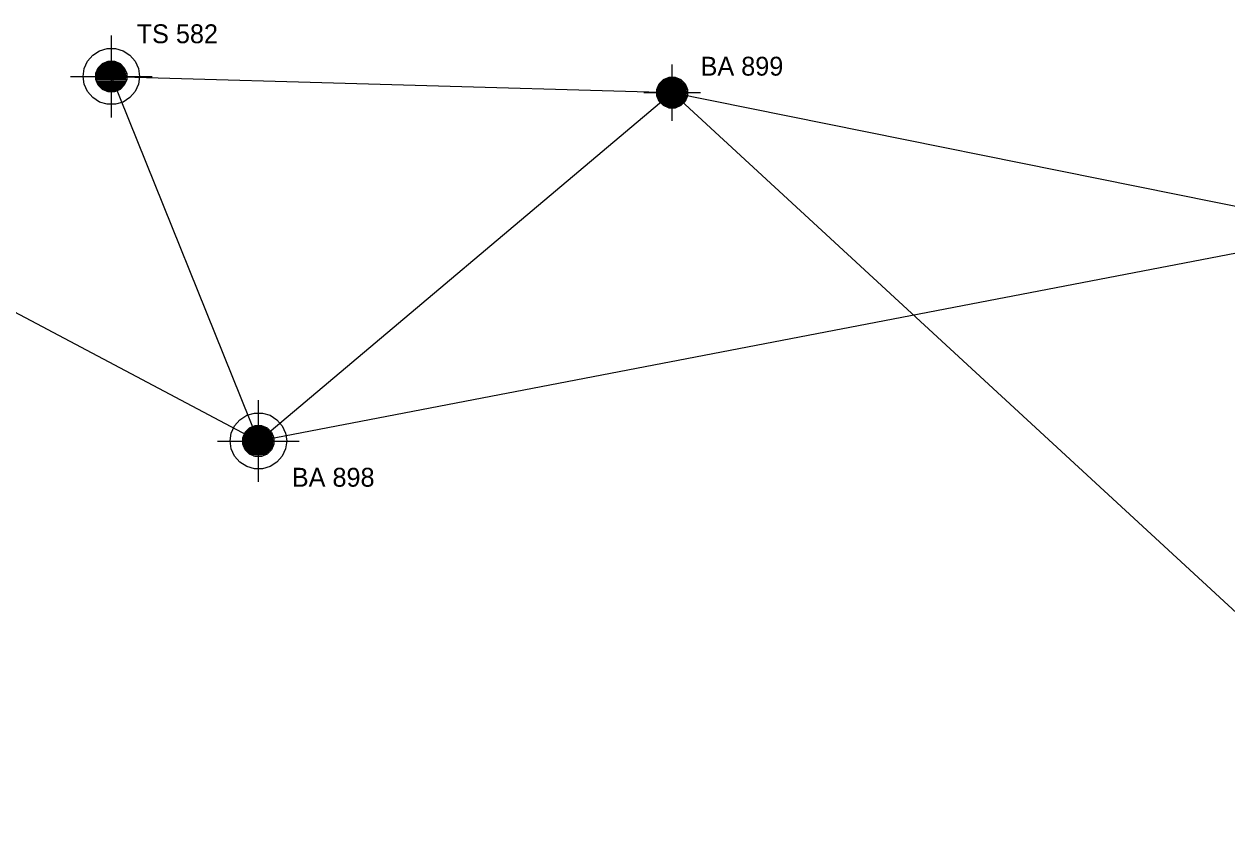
# Model space of a CAD drawing. Extents: x -346533 to -339969, y -1273090 to -1271585.
# Drawn here: x -345644.6 to -345166.4, y -1272777.1 to -1272455.2 of the extents above; entities that cross this region are included whole.
import ezdxf

# ---------------------------------------------------------------- set-up
doc = ezdxf.new("R2010")
doc.units = 0
for name, color, linetype in [('BP_11', 7, 'Continuous'), ('BP_12', 7, 'Continuous'), ('BP_14', 7, 'Continuous')]:
    doc.layers.add(name, color=color, linetype=linetype)

msp = doc.modelspace()

# ---------------------------------------------------------------- linework, layer by layer
at = {"layer": 'BP_11'}
for points in [[(-345609.9, -1272492.29), (-345609.9, -1272485.94), (-345609.9, -1272479.59), (-345609.9, -1272473.24), (-345609.9, -1272466.89), (-345609.9, -1272460.54), (-345609.9, -1272459.79)], [(-345609.9, -1272469.89), (-345608.7, -1272469.89), (-345606.45, -1272470.84), (-345604.75, -1272472.54), (-345603.8, -1272474.79), (-345603.8, -1272477.24), (-345604.75, -1272479.49), (-345606.45, -1272481.19), (-345608.7, -1272482.14), (-345611.15, -1272482.14), (-345613.4, -1272481.19), (-345615.1, -1272479.49), (-345616.05, -1272477.24), (-345616.05, -1272474.79), (-345615.1, -1272472.54), (-345613.4, -1272470.84), (-345611.15, -1272469.89), (-345609.95, -1272469.89), (-345608.15, -1272470.24), (-345611.75, -1272470.24), (-345612.55, -1272470.64), (-345607.35, -1272470.64), (-345606.55, -1272471.04), (-345612.9, -1272471.04), (-345613.35, -1272471.04), (-345613.75, -1272471.44), (-345607.4, -1272471.44), (-345606.15, -1272471.44), (-345605.75, -1272471.84), (-345612.1, -1272471.84), (-345614.15, -1272471.84), (-345614.55, -1272472.24), (-345608.2, -1272472.24), (-345605.35, -1272472.24), (-345604.95, -1272472.64), (-345611.3, -1272472.64), (-345614.95, -1272472.64), (-345614.95, -1272473.04), (-345608.6, -1272473.04), (-345604.95, -1272473.04), (-345604.55, -1272473.44), (-345610.9, -1272473.44), (-345615.35, -1272473.44), (-345615.35, -1272473.84), (-345609, -1272473.84), (-345604.55, -1272473.84), (-345604.55, -1272474.24), (-345610.9, -1272474.24), (-345615.35, -1272474.24), (-345615.75, -1272474.64), (-345609.4, -1272474.64), (-345604.15, -1272474.64), (-345604.15, -1272475.04), (-345610.5, -1272475.04), (-345615.75, -1272475.04), (-345615.75, -1272475.44), (-345609.4, -1272475.44), (-345604.15, -1272475.44), (-345604.15, -1272475.84), (-345610.5, -1272475.84), (-345615.75, -1272475.84), (-345615.75, -1272476.24), (-345609.4, -1272476.24), (-345604.15, -1272476.24), (-345604.15, -1272476.64), (-345610.5, -1272476.64), (-345615.75, -1272476.64), (-345615.75, -1272477.04), (-345609.4, -1272477.04), (-345604.15, -1272477.04), (-345604.15, -1272477.44), (-345610.5, -1272477.44), (-345615.75, -1272477.44), (-345615.75, -1272477.84), (-345609.4, -1272477.84), (-345604.15, -1272477.84), (-345604.55, -1272478.24), (-345610.9, -1272478.24), (-345615.35, -1272478.24), (-345615.35, -1272478.64), (-345609, -1272478.64), (-345604.55, -1272478.64), (-345604.95, -1272479.04), (-345611.3, -1272479.04), (-345614.95, -1272479.04), (-345614.95, -1272479.44), (-345608.6, -1272479.44), (-345604.95, -1272479.44), (-345605.35, -1272479.84), (-345611.7, -1272479.84), (-345614.55, -1272479.84), (-345614.15, -1272480.24), (-345607.8, -1272480.24), (-345605.75, -1272480.24), (-345606.15, -1272480.64), (-345612.5, -1272480.64), (-345613.75, -1272480.64), (-345613.35, -1272481.04), (-345607, -1272481.04), (-345606.55, -1272481.04)], [(-345386.94, -1272493.72), (-345386.94, -1272487.37), (-345386.94, -1272481.02), (-345386.94, -1272474.67), (-345386.94, -1272471.22)], [(-345626.15, -1272476.04), (-345619.8, -1272476.04), (-345613.45, -1272476.04), (-345607.1, -1272476.04), (-345600.75, -1272476.04), (-345594.4, -1272476.04), (-345593.65, -1272476.04)], [(-345386.94, -1272476.32), (-345385.74, -1272476.32), (-345383.49, -1272477.27), (-345381.79, -1272478.97), (-345380.84, -1272481.22), (-345380.84, -1272483.67), (-345381.79, -1272485.92), (-345383.49, -1272487.62), (-345385.74, -1272488.57), (-345388.19, -1272488.57), (-345390.44, -1272487.62), (-345392.14, -1272485.92), (-345393.09, -1272483.67), (-345393.09, -1272481.22), (-345392.14, -1272478.97), (-345390.44, -1272477.27), (-345388.19, -1272476.32), (-345386.99, -1272476.32), (-345385.19, -1272476.67), (-345388.79, -1272476.67), (-345389.59, -1272477.07), (-345384.39, -1272477.07), (-345383.59, -1272477.47), (-345389.94, -1272477.47), (-345390.39, -1272477.47), (-345390.79, -1272477.87), (-345384.44, -1272477.87), (-345383.19, -1272477.87), (-345382.79, -1272478.27), (-345389.14, -1272478.27), (-345391.19, -1272478.27), (-345391.59, -1272478.67), (-345385.24, -1272478.67), (-345382.39, -1272478.67), (-345381.99, -1272479.07), (-345388.34, -1272479.07), (-345391.99, -1272479.07), (-345391.99, -1272479.47), (-345385.64, -1272479.47), (-345381.99, -1272479.47), (-345381.59, -1272479.87), (-345387.94, -1272479.87), (-345392.39, -1272479.87), (-345392.39, -1272480.27), (-345386.04, -1272480.27), (-345381.59, -1272480.27), (-345381.19, -1272480.67), (-345387.54, -1272480.67), (-345392.79, -1272480.67), (-345392.79, -1272481.07), (-345386.44, -1272481.07), (-345381.19, -1272481.07), (-345381.19, -1272481.47), (-345387.54, -1272481.47), (-345392.79, -1272481.47), (-345392.79, -1272481.87), (-345386.44, -1272481.87), (-345381.19, -1272481.87), (-345381.19, -1272482.27), (-345387.54, -1272482.27), (-345392.79, -1272482.27), (-345392.79, -1272482.67), (-345386.44, -1272482.67), (-345381.19, -1272482.67), (-345381.19, -1272483.07), (-345387.54, -1272483.07), (-345392.79, -1272483.07), (-345392.79, -1272483.47), (-345386.44, -1272483.47), (-345381.19, -1272483.47), (-345381.19, -1272483.87), (-345387.54, -1272483.87), (-345392.79, -1272483.87), (-345392.79, -1272484.27), (-345386.44, -1272484.27), (-345381.19, -1272484.27), (-345381.59, -1272484.67), (-345387.94, -1272484.67), (-345392.39, -1272484.67), (-345392.39, -1272485.07), (-345386.04, -1272485.07), (-345381.59, -1272485.07), (-345381.99, -1272485.47), (-345388.34, -1272485.47), (-345391.99, -1272485.47), (-345391.99, -1272485.87), (-345385.64, -1272485.87), (-345381.99, -1272485.87), (-345382.39, -1272486.27), (-345388.74, -1272486.27), (-345391.59, -1272486.27), (-345391.19, -1272486.67), (-345384.84, -1272486.67), (-345382.79, -1272486.67), (-345383.19, -1272487.07), (-345389.54, -1272487.07), (-345390.79, -1272487.07), (-345390.39, -1272487.47), (-345384.04, -1272487.47), (-345383.59, -1272487.47)], [(-345606.55, -1272481.04), (-345607.35, -1272481.44), (-345612.55, -1272481.44), (-345611.75, -1272481.84), (-345608.15, -1272481.84)], [(-345398.19, -1272482.47), (-345391.84, -1272482.47), (-345385.49, -1272482.47), (-345379.14, -1272482.47), (-345375.69, -1272482.47)], [(-345383.59, -1272487.47), (-345384.39, -1272487.87), (-345389.59, -1272487.87), (-345388.79, -1272488.27), (-345385.19, -1272488.27)], [(-345551.44, -1272637.21), (-345551.44, -1272630.86), (-345551.44, -1272624.51), (-345551.44, -1272618.16), (-345551.44, -1272611.81), (-345551.44, -1272605.46), (-345551.44, -1272604.71)], [(-345551.44, -1272614.81), (-345550.24, -1272614.81), (-345547.99, -1272615.76), (-345546.29, -1272617.46), (-345545.34, -1272619.71), (-345545.34, -1272622.16), (-345546.29, -1272624.41), (-345547.99, -1272626.11), (-345550.24, -1272627.06), (-345552.69, -1272627.06), (-345554.94, -1272626.11), (-345556.64, -1272624.41), (-345557.59, -1272622.16), (-345557.59, -1272619.71), (-345556.64, -1272617.46), (-345554.94, -1272615.76), (-345552.69, -1272614.81), (-345551.49, -1272614.81), (-345549.69, -1272615.16), (-345553.29, -1272615.16), (-345554.09, -1272615.56), (-345548.89, -1272615.56), (-345548.09, -1272615.96), (-345554.44, -1272615.96), (-345554.89, -1272615.96), (-345555.29, -1272616.36), (-345548.94, -1272616.36), (-345547.69, -1272616.36), (-345547.29, -1272616.76), (-345553.64, -1272616.76), (-345555.69, -1272616.76), (-345556.09, -1272617.16), (-345549.74, -1272617.16), (-345546.89, -1272617.16), (-345546.49, -1272617.56), (-345552.84, -1272617.56), (-345556.49, -1272617.56), (-345556.49, -1272617.96), (-345550.14, -1272617.96), (-345546.49, -1272617.96), (-345546.09, -1272618.36), (-345552.44, -1272618.36), (-345556.89, -1272618.36), (-345556.89, -1272618.76), (-345550.54, -1272618.76), (-345546.09, -1272618.76), (-345546.09, -1272619.16), (-345552.44, -1272619.16), (-345556.89, -1272619.16), (-345557.29, -1272619.56), (-345550.94, -1272619.56), (-345545.69, -1272619.56), (-345545.69, -1272619.96), (-345552.04, -1272619.96), (-345557.29, -1272619.96), (-345557.29, -1272620.36), (-345550.94, -1272620.36), (-345545.69, -1272620.36), (-345545.69, -1272620.76), (-345552.04, -1272620.76), (-345557.29, -1272620.76), (-345557.29, -1272621.16), (-345550.94, -1272621.16), (-345545.69, -1272621.16), (-345545.69, -1272621.56), (-345552.04, -1272621.56), (-345557.29, -1272621.56), (-345557.29, -1272621.96), (-345550.94, -1272621.96), (-345545.69, -1272621.96), (-345545.69, -1272622.36), (-345552.04, -1272622.36), (-345557.29, -1272622.36), (-345557.29, -1272622.76), (-345550.94, -1272622.76), (-345545.69, -1272622.76), (-345546.09, -1272623.16), (-345552.44, -1272623.16), (-345556.89, -1272623.16), (-345556.89, -1272623.56), (-345550.54, -1272623.56), (-345546.09, -1272623.56), (-345546.49, -1272623.96), (-345552.84, -1272623.96), (-345556.49, -1272623.96), (-345556.49, -1272624.36), (-345550.14, -1272624.36), (-345546.49, -1272624.36), (-345546.89, -1272624.76), (-345553.24, -1272624.76), (-345556.09, -1272624.76), (-345555.69, -1272625.16), (-345549.34, -1272625.16), (-345547.29, -1272625.16), (-345547.69, -1272625.56), (-345554.04, -1272625.56), (-345555.29, -1272625.56), (-345554.89, -1272625.96), (-345548.54, -1272625.96), (-345548.09, -1272625.96)], [(-345567.69, -1272620.96), (-345561.34, -1272620.96), (-345554.99, -1272620.96), (-345548.64, -1272620.96), (-345542.29, -1272620.96), (-345535.94, -1272620.96), (-345535.19, -1272620.96)], [(-345548.09, -1272625.96), (-345548.89, -1272626.36), (-345554.09, -1272626.36), (-345553.29, -1272626.76), (-345549.69, -1272626.76)]]:
    msp.add_lwpolyline(points, dxfattribs=at)
for points in [[(-345608.3, -1272464.89), (-345605.25, -1272465.79), (-345602.55, -1272467.54), (-345600.45, -1272469.94), (-345599.1, -1272472.84), (-345598.65, -1272475.99), (-345599.1, -1272479.14), (-345600.45, -1272482.04), (-345602.55, -1272484.44), (-345605.25, -1272486.19), (-345608.3, -1272487.09), (-345611.5, -1272487.09), (-345614.55, -1272486.19), (-345617.25, -1272484.44), (-345619.35, -1272482.04), (-345620.7, -1272479.14), (-345621.15, -1272475.99), (-345620.7, -1272472.84), (-345619.35, -1272469.94), (-345617.25, -1272467.54), (-345614.55, -1272465.79), (-345611.5, -1272464.89)], [(-345385.74, -1272476.32), (-345383.49, -1272477.27), (-345381.79, -1272478.97), (-345380.84, -1272481.22), (-345380.84, -1272483.67), (-345381.79, -1272485.92), (-345383.49, -1272487.62), (-345385.74, -1272488.57), (-345388.19, -1272488.57), (-345390.44, -1272487.62), (-345392.14, -1272485.92), (-345393.09, -1272483.67), (-345393.09, -1272481.22), (-345392.14, -1272478.97), (-345390.44, -1272477.27), (-345388.19, -1272476.32)], [(-345549.84, -1272609.81), (-345546.79, -1272610.71), (-345544.09, -1272612.46), (-345541.99, -1272614.86), (-345540.64, -1272617.76), (-345540.19, -1272620.91), (-345540.64, -1272624.06), (-345541.99, -1272626.96), (-345544.09, -1272629.36), (-345546.79, -1272631.11), (-345549.84, -1272632.01), (-345553.04, -1272632.01), (-345556.09, -1272631.11), (-345558.79, -1272629.36), (-345560.89, -1272626.96), (-345562.24, -1272624.06), (-345562.69, -1272620.91), (-345562.24, -1272617.76), (-345560.89, -1272614.86), (-345558.79, -1272612.46), (-345556.09, -1272610.71), (-345553.04, -1272609.81)]]:
    msp.add_lwpolyline(points, close=True, dxfattribs=at)
at = {"layer": 'BP_14'}
for p, q in [((-345551.44, -1272620.96), (-345609.9, -1272476.04)), ((-345609.9, -1272476.04), (-345386.94, -1272482.47)), ((-345551.44, -1272620.96), (-345386.94, -1272482.47)), ((-345386.94, -1272482.47), (-345115.54, -1272537.22)), ((-345386.94, -1272482.47), (-345067.32, -1272777.11)), ((-345749.57, -1272516.01), (-345551.44, -1272620.96)), ((-345115.54, -1272537.22), (-345551.44, -1272620.96))]:
    msp.add_line(p, q, dxfattribs=at)

# ---------------------------------------------------------------- texts
at = {"layer": 'BP_12'}
for s, p in [('TS 582', (-345599.83, -1272462.82)), ('BA 899', (-345375.64, -1272475.7)), ('BA 898', (-345538.15, -1272639.09))]:
    msp.add_text(s, height=7.5, dxfattribs=at).set_placement(p)

doc.saveas('drawing.dxf')
